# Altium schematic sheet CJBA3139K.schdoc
size 127 x 101 mm
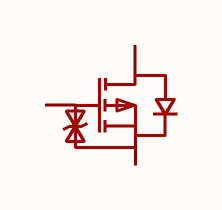
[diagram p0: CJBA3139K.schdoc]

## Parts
Q?  cjba3139k  [DFN1006-3L_L1.0-W0.6-LS1.0-BR]  (value not drawn)

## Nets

Not connected (* = marked no-connect by the designer): Q? 1(G) 2(S) 3(D)

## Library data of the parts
Q? = cjba3139k: 数量:1个P沟道;漏源电压(Vdss):20V;连续漏极电流(Id):660mA;导通电阻(RDS(on)):520mΩ@4.5V;耗散功率(Pd):100mW;阈值电压(Vgs(th)):350mV;; Manufacturer: CJ(江苏长电/长晶); AddInBom: yes; ModelId: cc686921d11847a99f974ae407b58fda; ModelName: DFN1006-3L_L1.0-W0.6-H0.4-LS1.0-BR; ModelTransform: 40.1574,24.4094,0,180,0,0,0,0,0; Number: 1个P沟道; Drain to Source Voltage: 20V; Current - Continuous Drain(Id): 660mA; Pd - Power Dissipation: 100mW; Gate Threshold Voltage (Vgs(th)): 350mV; Input Capacitance(Ciss): 113pF; Reverse Transfer Capacitance (Crss@Vds): 9pF; Type: P沟道; Output Capacitance(Coss): 15pF; Vgs: ±12V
